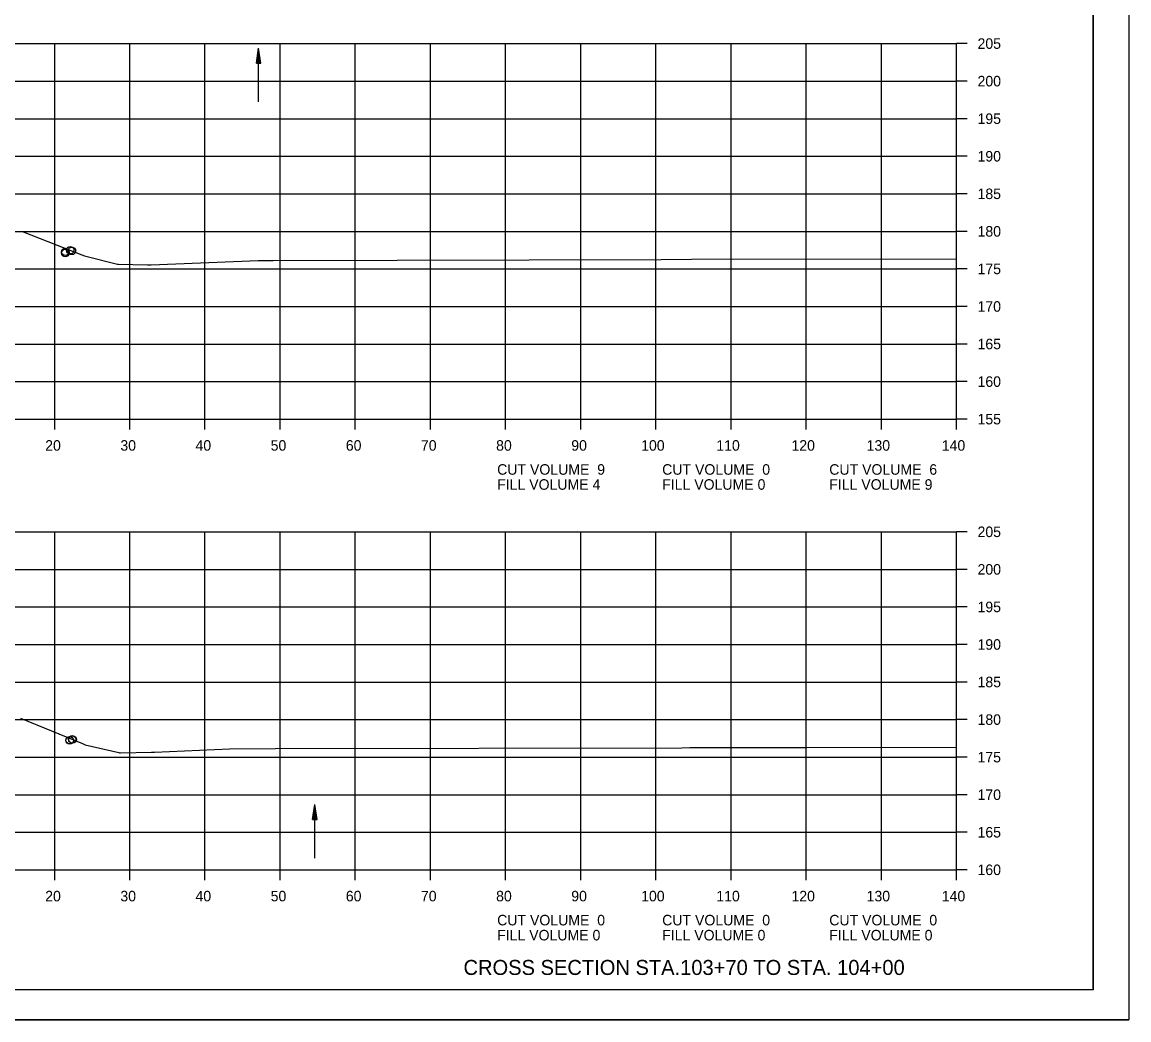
# Model space of a CAD drawing. Extents: x 1372132 to 1372465, y 380083 to 381790.
# Drawn here: x 1372317.7 to 1372464.9, y 380083.5 to 380216.3 of the extents above; entities that cross this region are included whole.
import ezdxf

# ---------------------------------------------------------------- set-up
doc = ezdxf.new("R2010")
doc.units = 0
for name, color, linetype in [('R_Axis', 7, 'Continuous'), ('R_Axis Annot', 7, 'Continuous'), ('R_Border', 7, 'Continuous'), ('R_Dimension', 7, 'Continuous'), ('R_Draft', 7, 'Continuous'), ('R_Exist Surface', 7, 'Continuous'), ('R_Grid', 7, 'Continuous'), ('R_No Plot', 7, 'Continuous')]:
    doc.layers.add(name, color=color, linetype=linetype)

msp = doc.modelspace()

# ---------------------------------------------------------------- linework, layer by layer
at = {"layer": 'R_Axis'}
for p, q in [((1372442.01, 380163.47), (1372442.01, 380213.47)), ((1372443.41, 380213.47), (1372442.01, 380213.47)), ((1372443.41, 380208.47), (1372442.01, 380208.47)), ((1372443.41, 380203.47), (1372442.01, 380203.47)), ((1372443.41, 380198.47), (1372442.01, 380198.47)), ((1372443.41, 380193.47), (1372442.01, 380193.47)), ((1372443.41, 380188.47), (1372442.01, 380188.47)), ((1372443.41, 380183.47), (1372442.01, 380183.47)), ((1372443.41, 380178.47), (1372442.01, 380178.47)), ((1372443.41, 380173.47), (1372442.01, 380173.47)), ((1372443.41, 380168.47), (1372442.01, 380168.47)), ((1372162.01, 380163.47), (1372442.01, 380163.47)), ((1372322.01, 380162.07), (1372322.01, 380163.47)), ((1372332.01, 380162.07), (1372332.01, 380163.47)), ((1372342.01, 380162.07), (1372342.01, 380163.47)), ((1372352.01, 380162.07), (1372352.01, 380163.47)), ((1372362.01, 380162.07), (1372362.01, 380163.47)), ((1372372.01, 380162.07), (1372372.01, 380163.47)), ((1372382.01, 380162.07), (1372382.01, 380163.47)), ((1372392.01, 380162.07), (1372392.01, 380163.47)), ((1372402.01, 380162.07), (1372402.01, 380163.47)), ((1372412.01, 380162.07), (1372412.01, 380163.47)), ((1372422.01, 380162.07), (1372422.01, 380163.47)), ((1372432.01, 380162.07), (1372432.01, 380163.47)), ((1372442.01, 380162.07), (1372442.01, 380163.47)), ((1372443.41, 380163.47), (1372442.01, 380163.47)), ((1372442.01, 380103.47), (1372442.01, 380148.47)), ((1372443.41, 380148.47), (1372442.01, 380148.47)), ((1372443.41, 380143.47), (1372442.01, 380143.47)), ((1372443.41, 380138.47), (1372442.01, 380138.47)), ((1372443.41, 380133.47), (1372442.01, 380133.47)), ((1372443.41, 380128.47), (1372442.01, 380128.47)), ((1372443.41, 380123.47), (1372442.01, 380123.47)), ((1372443.41, 380118.47), (1372442.01, 380118.47)), ((1372443.41, 380113.47), (1372442.01, 380113.47)), ((1372443.41, 380108.47), (1372442.01, 380108.47)), ((1372162.01, 380103.47), (1372442.01, 380103.47)), ((1372322.01, 380102.07), (1372322.01, 380103.47)), ((1372332.01, 380102.07), (1372332.01, 380103.47)), ((1372342.01, 380102.07), (1372342.01, 380103.47)), ((1372352.01, 380102.07), (1372352.01, 380103.47)), ((1372362.01, 380102.07), (1372362.01, 380103.47)), ((1372372.01, 380102.07), (1372372.01, 380103.47)), ((1372382.01, 380102.07), (1372382.01, 380103.47)), ((1372392.01, 380102.07), (1372392.01, 380103.47)), ((1372402.01, 380102.07), (1372402.01, 380103.47)), ((1372412.01, 380102.07), (1372412.01, 380103.47)), ((1372422.01, 380102.07), (1372422.01, 380103.47)), ((1372432.01, 380102.07), (1372432.01, 380103.47)), ((1372442.01, 380102.07), (1372442.01, 380103.47)), ((1372443.41, 380103.47), (1372442.01, 380103.47))]:
    msp.add_line(p, q, dxfattribs=at)
at = {"layer": 'R_Border'}
for q in [(1372460.19, 380292.93), (1372144.01, 380087.47)]:
    msp.add_line((1372460.19, 380087.47), q, dxfattribs=at)
at = {"layer": 'R_Dimension'}
for p, q in [((1372348.85, 380210.87), (1372349.15, 380212.87)), ((1372348.85, 380210.87), (1372349.15, 380212.87)), ((1372348.9, 380210.87), (1372349.15, 380212.54)), ((1372348.9, 380210.87), (1372349.15, 380212.54)), ((1372348.95, 380210.87), (1372349.15, 380212.2)), ((1372348.95, 380210.87), (1372349.15, 380212.2)), ((1372349, 380210.87), (1372349.15, 380211.86)), ((1372349, 380210.87), (1372349.15, 380211.86)), ((1372349.45, 380210.87), (1372349.15, 380212.87)), ((1372349.45, 380210.87), (1372349.15, 380212.87)), ((1372349.4, 380210.87), (1372349.15, 380212.54)), ((1372349.4, 380210.87), (1372349.15, 380212.54)), ((1372349.35, 380210.87), (1372349.15, 380212.2)), ((1372349.35, 380210.87), (1372349.15, 380212.2)), ((1372349.3, 380210.87), (1372349.15, 380211.86)), ((1372349.3, 380210.87), (1372349.15, 380211.86)), ((1372348.85, 380210.87), (1372349.45, 380210.87)), ((1372348.85, 380210.87), (1372349.45, 380210.87)), ((1372349.06, 380210.87), (1372349.15, 380211.52)), ((1372349.06, 380210.87), (1372349.15, 380211.52)), ((1372349.11, 380210.87), (1372349.15, 380211.19)), ((1372349.11, 380210.87), (1372349.15, 380211.19)), ((1372349.25, 380210.87), (1372349.15, 380211.52)), ((1372349.25, 380210.87), (1372349.15, 380211.52)), ((1372349.2, 380210.87), (1372349.15, 380211.19)), ((1372349.2, 380210.87), (1372349.15, 380211.19)), ((1372356.34, 380110.18), (1372356.64, 380112.18)), ((1372356.34, 380110.18), (1372356.64, 380112.18)), ((1372356.39, 380110.18), (1372356.64, 380111.85)), ((1372356.39, 380110.18), (1372356.64, 380111.85)), ((1372356.44, 380110.18), (1372356.64, 380111.51)), ((1372356.44, 380110.18), (1372356.64, 380111.51)), ((1372356.94, 380110.18), (1372356.64, 380112.18)), ((1372356.94, 380110.18), (1372356.64, 380112.18)), ((1372356.89, 380110.18), (1372356.64, 380111.85)), ((1372356.89, 380110.18), (1372356.64, 380111.85)), ((1372356.84, 380110.18), (1372356.64, 380111.51)), ((1372356.84, 380110.18), (1372356.64, 380111.51)), ((1372356.34, 380110.18), (1372356.94, 380110.18)), ((1372356.34, 380110.18), (1372356.94, 380110.18)), ((1372356.49, 380110.18), (1372356.64, 380111.17)), ((1372356.49, 380110.18), (1372356.64, 380111.17)), ((1372356.54, 380110.18), (1372356.64, 380110.83)), ((1372356.54, 380110.18), (1372356.64, 380110.83)), ((1372356.59, 380110.18), (1372356.64, 380110.5)), ((1372356.59, 380110.18), (1372356.64, 380110.5)), ((1372356.79, 380110.18), (1372356.64, 380111.17)), ((1372356.79, 380110.18), (1372356.64, 380111.17)), ((1372356.74, 380110.18), (1372356.64, 380110.83)), ((1372356.74, 380110.18), (1372356.64, 380110.83)), ((1372356.68, 380110.18), (1372356.64, 380110.5)), ((1372356.68, 380110.18), (1372356.64, 380110.5))]:
    msp.add_line(p, q, dxfattribs=at)
at = {"layer": 'R_Draft'}
for p, q in [((1372349.15, 380205.73), (1372349.15, 380212.87)), ((1372356.64, 380105.04), (1372356.64, 380112.18))]:
    msp.add_line(p, q, dxfattribs=at)
at = {"layer": 'R_Exist Surface'}
for points in [[(1372317.48, 380188.44), (1372317.82, 380188.4), (1372325.61, 380185.36), (1372325.97, 380185.22), (1372330.37, 380184.12), (1372330.43, 380184.1), (1372330.49, 380184.1), (1372334.37, 380184.01), (1372334.85, 380184.03), (1372349.07, 380184.6), (1372351.09, 380184.61), (1372367.6, 380184.65), (1372402.71, 380184.74), (1372406.77, 380184.75), (1372442.01, 380184.81)], [(1372317.45, 380123.67), (1372325.71, 380120.28), (1372326.09, 380120.12), (1372330.53, 380119.07), (1372330.64, 380119.05), (1372330.75, 380119.05), (1372334.88, 380119.13), (1372335.29, 380119.15), (1372345.26, 380119.58), (1372351.39, 380119.6), (1372405.47, 380119.73), (1372406.52, 380119.74), (1372422.09, 380119.76), (1372442.01, 380119.79)]]:
    msp.add_lwpolyline(points, dxfattribs=at)
at = {"layer": 'R_Grid'}
for p, q in [((1372162.01, 380213.47), (1372442.01, 380213.47)), ((1372322.01, 380163.47), (1372322.01, 380213.47)), ((1372332.01, 380163.47), (1372332.01, 380213.47)), ((1372342.01, 380163.47), (1372342.01, 380213.47)), ((1372352.01, 380163.47), (1372352.01, 380213.47)), ((1372362.01, 380163.47), (1372362.01, 380213.47)), ((1372372.01, 380163.47), (1372372.01, 380213.47)), ((1372382.01, 380163.47), (1372382.01, 380213.47)), ((1372392.01, 380163.47), (1372392.01, 380213.47)), ((1372402.01, 380163.47), (1372402.01, 380213.47)), ((1372412.01, 380163.47), (1372412.01, 380213.47)), ((1372422.01, 380163.47), (1372422.01, 380213.47)), ((1372432.01, 380163.47), (1372432.01, 380213.47)), ((1372442.01, 380163.47), (1372442.01, 380213.47)), ((1372162.01, 380208.47), (1372442.01, 380208.47)), ((1372162.01, 380203.47), (1372442.01, 380203.47)), ((1372162.01, 380198.47), (1372442.01, 380198.47)), ((1372162.01, 380193.47), (1372442.01, 380193.47)), ((1372162.01, 380188.47), (1372442.01, 380188.47)), ((1372162.01, 380183.47), (1372442.01, 380183.47)), ((1372162.01, 380178.47), (1372442.01, 380178.47)), ((1372162.01, 380173.47), (1372442.01, 380173.47)), ((1372162.01, 380168.47), (1372442.01, 380168.47)), ((1372162.01, 380163.47), (1372442.01, 380163.47)), ((1372162.01, 380148.47), (1372442.01, 380148.47)), ((1372322.01, 380103.47), (1372322.01, 380148.47)), ((1372332.01, 380103.47), (1372332.01, 380148.47)), ((1372342.01, 380103.47), (1372342.01, 380148.47)), ((1372352.01, 380103.47), (1372352.01, 380148.47)), ((1372362.01, 380103.47), (1372362.01, 380148.47)), ((1372372.01, 380103.47), (1372372.01, 380148.47)), ((1372382.01, 380103.47), (1372382.01, 380148.47)), ((1372392.01, 380103.47), (1372392.01, 380148.47)), ((1372402.01, 380103.47), (1372402.01, 380148.47)), ((1372412.01, 380103.47), (1372412.01, 380148.47)), ((1372422.01, 380103.47), (1372422.01, 380148.47)), ((1372432.01, 380103.47), (1372432.01, 380148.47)), ((1372442.01, 380103.47), (1372442.01, 380148.47)), ((1372162.01, 380143.47), (1372442.01, 380143.47)), ((1372162.01, 380138.47), (1372442.01, 380138.47)), ((1372162.01, 380133.47), (1372442.01, 380133.47)), ((1372162.01, 380128.47), (1372442.01, 380128.47)), ((1372162.01, 380123.47), (1372442.01, 380123.47)), ((1372162.01, 380118.47), (1372442.01, 380118.47)), ((1372162.01, 380113.47), (1372442.01, 380113.47)), ((1372162.01, 380108.47), (1372442.01, 380108.47)), ((1372162.01, 380103.47), (1372442.01, 380103.47))]:
    msp.add_line(p, q, dxfattribs=at)
at = {"layer": 'R_No Plot'}
msp.add_line((1372131.61, 380083.49), (1372464.95, 380083.49), dxfattribs=at)
for points in [[(1372131.61, 380296.83), (1372464.95, 380296.83), (1372464.95, 380083.49), (1372131.61, 380083.49)], [(1372377.93, 380292.93), (1372377.93, 380283.05), (1372413.67, 380283.05), (1372413.67, 380280.13), (1372436.87, 380280.13), (1372436.87, 380255.8), (1372460.19, 380255.8), (1372460.19, 380087.47), (1372144.01, 380087.47), (1372144.01, 380292.93)]]:
    msp.add_lwpolyline(points, close=True, dxfattribs=at)
for centre in [(1372323.43, 380185.74), (1372323.43, 380185.58), (1372324.08, 380185.96), (1372324.3, 380185.87), (1372324.01, 380120.73), (1372324.01, 380120.69), (1372324.34, 380120.84), (1372324.4, 380120.82)]:
    msp.add_circle(centre, 0.5, dxfattribs=at)

# ---------------------------------------------------------------- texts
at = {"layer": 'R_Axis Annot'}
for s, p in [('205', (1372444.81, 380212.77)), ('200', (1372444.81, 380207.77)), ('195', (1372444.81, 380202.77)), ('190', (1372444.81, 380197.77)), ('185', (1372444.81, 380192.77)), ('180', (1372444.81, 380187.77)), ('175', (1372444.81, 380182.77)), ('170', (1372444.81, 380177.77)), ('165', (1372444.81, 380172.77)), ('160', (1372444.81, 380167.77)), ('155', (1372444.81, 380162.77)), ('20', (1372320.75, 380159.27)), ('30', (1372330.75, 380159.27)), ('40', (1372340.75, 380159.27)), ('50', (1372350.75, 380159.27)), ('60', (1372360.75, 380159.27)), ('70', (1372370.75, 380159.27)), ('80', (1372380.75, 380159.27)), ('90', (1372390.75, 380159.27)), ('100', (1372400.05, 380159.27)), ('110', (1372410.05, 380159.27)), ('120', (1372420.05, 380159.27)), ('130', (1372430.05, 380159.27)), ('140', (1372440.05, 380159.27)), ('CUT VOLUME  9', (1372380.89, 380156.07)), ('CUT VOLUME  0', (1372402.85, 380156.07)), ('CUT VOLUME  6', (1372425.08, 380156.07)), ('FILL VOLUME 4', (1372380.89, 380154.07)), ('FILL VOLUME 0', (1372402.85, 380154.07)), ('FILL VOLUME 9', (1372425.08, 380154.07)), ('205', (1372444.81, 380147.77)), ('200', (1372444.81, 380142.77)), ('195', (1372444.81, 380137.77)), ('190', (1372444.81, 380132.77)), ('185', (1372444.81, 380127.77)), ('180', (1372444.81, 380122.77)), ('175', (1372444.81, 380117.77)), ('170', (1372444.81, 380112.77)), ('165', (1372444.81, 380107.77)), ('160', (1372444.81, 380102.77)), ('20', (1372320.75, 380099.27)), ('30', (1372330.75, 380099.27)), ('40', (1372340.75, 380099.27)), ('50', (1372350.75, 380099.27)), ('60', (1372360.75, 380099.27)), ('70', (1372370.75, 380099.27)), ('80', (1372380.75, 380099.27)), ('90', (1372390.75, 380099.27)), ('100', (1372400.05, 380099.27)), ('110', (1372410.05, 380099.27)), ('120', (1372420.05, 380099.27)), ('130', (1372430.05, 380099.27)), ('140', (1372440.05, 380099.27)), ('CUT VOLUME  0', (1372380.89, 380096.07)), ('CUT VOLUME  0', (1372402.85, 380096.07)), ('CUT VOLUME  0', (1372425.08, 380096.07)), ('FILL VOLUME 0', (1372380.89, 380094.07)), ('FILL VOLUME 0', (1372402.85, 380094.07)), ('FILL VOLUME 0', (1372425.08, 380094.07))]:
    msp.add_text(s, height=1.4, dxfattribs=at).set_placement(p)
at = {"layer": 'R_Draft'}
msp.add_text('CROSS SECTION STA.103+70 TO STA. 104+00', height=2, dxfattribs=at).set_placement((1372376.41, 380089.47))

doc.saveas('drawing.dxf')
